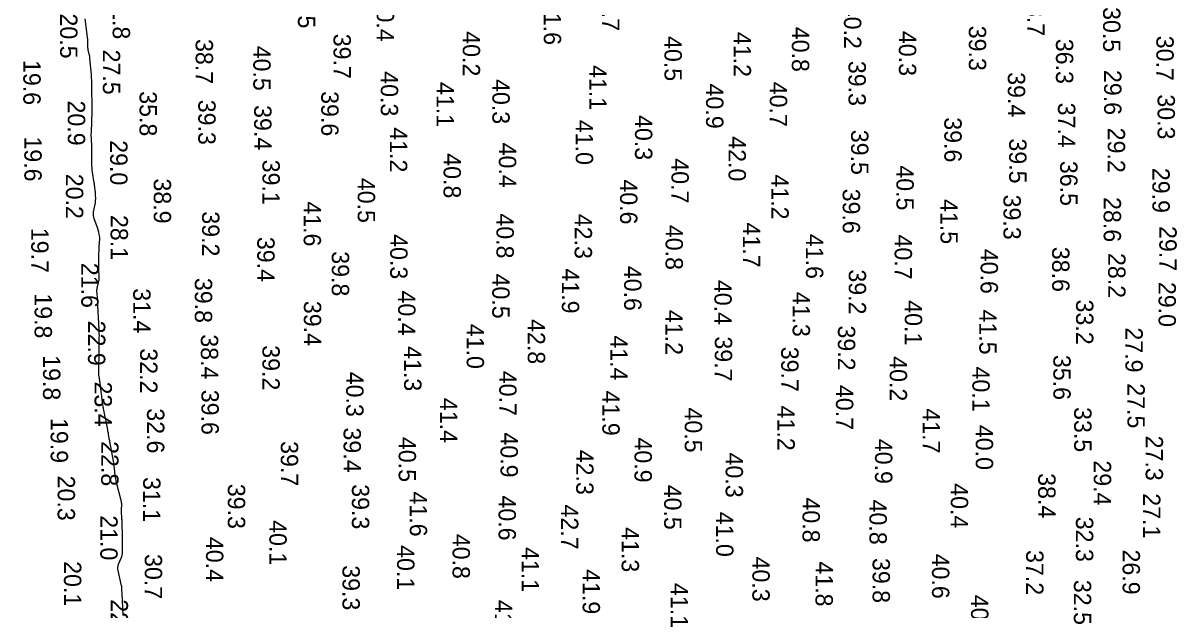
# Model space of a CAD drawing. Extents: x 1178573 to 1187098, y 693282 to 751751.
# Drawn here: x 1181240 to 1182072, y 696180 to 696604 of the extents above; entities that cross this region are included whole.
import ezdxf

# ---------------------------------------------------------------- set-up
doc = ezdxf.new("R2010")
doc.units = 0
doc.layers.add('V-HYDS-MAJR', color=7, linetype='Continuous')
doc.layers.add('V-HYDS-SOUN', color=7, linetype='Continuous')

msp = doc.modelspace()

# ---------------------------------------------------------------- linework, layer by layer
at = {"layer": 'V-HYDS-MAJR'}
msp.add_lwpolyline([(1181311.87, 696176.51), (1181311.14, 696192.46), (1181311.13, 696192.69), (1181311.11, 696192.92), (1181311.08, 696193.15), (1181311.06, 696193.38), (1181310.94, 696194.29), (1181310.91, 696194.52), (1181310.9, 696194.75), (1181310.89, 696194.98), (1181310.89, 696195.21), (1181310.92, 696196.65), (1181310.92, 696196.96), (1181310.9, 696197.27), (1181310.86, 696197.59), (1181310.8, 696197.9), (1181308.26, 696208.79), (1181308.08, 696209.95), (1181308.08, 696211.1), (1181308.27, 696212.23), (1181308.64, 696213.35), (1181310.47, 696217.79), (1181310.87, 696218.91), (1181311.16, 696220.05), (1181311.34, 696221.22), (1181311.4, 696222.41), (1181311.44, 696227.33), (1181311.44, 696228.54), (1181311.44, 696229.76), (1181311.42, 696230.98), (1181311.4, 696232.2), (1181311.1, 696244.47), (1181311.08, 696245.18), (1181311.05, 696245.9), (1181311.01, 696246.61), (1181310.96, 696247.32), (1181310.77, 696250.18), (1181310.73, 696250.89), (1181310.71, 696251.6), (1181310.7, 696252.32), (1181310.72, 696253.03), (1181310.82, 696256.22), (1181310.82, 696256.99), (1181310.76, 696257.75), (1181310.65, 696258.51), (1181310.49, 696259.26), (1181307.2, 696272.37), (1181306.9, 696273.64), (1181306.64, 696274.92), (1181306.42, 696276.21), (1181306.25, 696277.5), (1181305.63, 696282.69), (1181305.47, 696283.99), (1181305.28, 696285.28), (1181305.08, 696286.57), (1181304.85, 696287.86), (1181302.48, 696300.71), (1181302.33, 696301.51), (1181302.19, 696302.31), (1181302.05, 696303.11), (1181301.91, 696303.91), (1181301.36, 696307.12), (1181301.22, 696307.92), (1181301.08, 696308.72), (1181300.93, 696309.52), (1181300.77, 696310.32), (1181297.73, 696325.75), (1181297.66, 696326.12), (1181297.59, 696326.49), (1181297.53, 696326.86), (1181297.47, 696327.22), (1181297.24, 696328.7), (1181297.18, 696329.07), (1181297.13, 696329.45), (1181297.07, 696329.82), (1181297.02, 696330.19), (1181294.96, 696345.94), (1181294.88, 696346.52), (1181294.81, 696347.1), (1181294.74, 696347.68), (1181294.68, 696348.27), (1181294.43, 696350.59), (1181294.38, 696351.18), (1181294.35, 696351.76), (1181294.33, 696352.34), (1181294.33, 696352.93), (1181294.55, 696366.87), (1181294.57, 696368.13), (1181294.59, 696369.4), (1181294.61, 696370.67), (1181294.63, 696371.93), (1181294.71, 696377), (1181294.72, 696378.26), (1181294.71, 696379.53), (1181294.67, 696380.79), (1181294.62, 696382.06), (1181294.09, 696391.88), (1181294.04, 696392.86), (1181293.99, 696393.83), (1181293.95, 696394.81), (1181293.91, 696395.78), (1181293.75, 696399.69), (1181293.71, 696400.66), (1181293.65, 696401.64), (1181293.59, 696402.61), (1181293.52, 696403.59), (1181293.01, 696410.4), (1181292.98, 696411.2), (1181293.03, 696412), (1181293.14, 696412.79), (1181293.32, 696413.57), (1181294.18, 696416.7), (1181294.37, 696417.48), (1181294.5, 696418.27), (1181294.57, 696419.07), (1181294.58, 696419.87), (1181294.41, 696427.49), (1181294.39, 696429.03), (1181294.38, 696430.57), (1181294.4, 696432.11), (1181294.43, 696433.65), (1181294.67, 696443.2), (1181294.69, 696443.78), (1181294.72, 696444.35), (1181294.77, 696444.92), (1181294.82, 696445.48), (1181295.07, 696447.76), (1181295.11, 696448.33), (1181295.1, 696448.89), (1181295.05, 696449.45), (1181294.95, 696450.01), (1181294.31, 696452.94), (1181294.15, 696453.61), (1181293.97, 696454.27), (1181293.77, 696454.93), (1181293.55, 696455.58), (1181291.06, 696462.41), (1181290.69, 696463.68), (1181290.49, 696464.97), (1181290.47, 696466.27), (1181290.62, 696467.58), (1181291.83, 696474.11), (1181291.94, 696474.82), (1181292.02, 696475.53), (1181292.06, 696476.24), (1181292.07, 696476.96), (1181292.03, 696479.82), (1181292.01, 696480.54), (1181291.97, 696481.25), (1181291.91, 696481.96), (1181291.82, 696482.68), (1181291.44, 696485.53), (1181291.34, 696486.24), (1181291.24, 696486.95), (1181291.13, 696487.66), (1181291.02, 696488.37), (1181289.8, 696496.1), (1181289.59, 696497.63), (1181289.44, 696499.16), (1181289.36, 696500.69), (1181289.33, 696502.24), (1181289.34, 696509.88), (1181289.34, 696511.13), (1181289.32, 696512.38), (1181289.28, 696513.63), (1181289.23, 696514.88), (1181289, 696519.89), (1181288.95, 696521.14), (1181288.94, 696522.39), (1181288.94, 696523.64), (1181288.98, 696524.89), (1181289.55, 696539.87), (1181289.56, 696540.01), (1181289.56, 696540.16), (1181289.57, 696540.3), (1181289.57, 696540.44), (1181289.6, 696541.11), (1181289.6, 696541.21), (1181289.6, 696541.31), (1181289.59, 696541.4), (1181289.59, 696541.5), (1181289.55, 696541.88), (1181289.54, 696541.98), (1181289.54, 696542.08), (1181289.54, 696542.17), (1181289.53, 696542.27), (1181289.4, 696557.69), (1181289.36, 696559.9), (1181289.27, 696562.11), (1181289.15, 696564.32), (1181288.98, 696566.52), (1181287.96, 696578.18), (1181287.88, 696578.96), (1181287.77, 696579.74), (1181287.63, 696580.52), (1181287.47, 696581.29), (1181286.76, 696584.4), (1181286.6, 696585.15), (1181286.5, 696585.9), (1181286.43, 696586.66), (1181286.4, 696587.43), (1181286.38, 696590.5), (1181286.36, 696591.27), (1181286.32, 696592.03), (1181286.26, 696592.79), (1181286.18, 696593.56), (1181284.51, 696606.81)], dxfattribs=at)

# ---------------------------------------------------------------- texts
at = {"layer": 'V-HYDS-SOUN'}
for s, p in [('39.5 ', (1181437.93, 696632.39)), ('41.7 ', (1181657.31, 696630.44)), ('31.8 ', (1181304.34, 696624.5)), ('40.4 ', (1181494.78, 696622.77)), ('38.7 ', (1181963.9, 696626.8)), ('41.6 ', (1181615.25, 696620.37)), ('40.2 ', (1181831.74, 696617.61)), ('30.5 ', (1182018.61, 696615.2)), ('20.5 ', (1181266.44, 696610.6)), ('40.2 ', (1181556.81, 696597.79)), ('41.2 ', (1181752.21, 696597.33)), ('40.8 ', (1181794.16, 696601.01)), ('40.3 ', (1181871.35, 696598.03)), ('39.3 ', (1181921.81, 696601.77)), ('38.7 ', (1181364.2, 696592.19)), ('39.7 ', (1181463.61, 696595.99)), ('40.5 ', (1181702.3, 696594.33)), ('36.3 ', (1181984.61, 696592.35)), ('30.7 ', (1182057.05, 696594.55)), ('27.5 ', (1181297.25, 696584.55)), ('40.5 ', (1181405.75, 696587.38)), ('19.6 ', (1181239.89, 696577.06)), ('41.1 ', (1181648.07, 696573.41)), ('39.3 ', (1181835.03, 696576.44)), ('40.3 ', (1181497.7, 696568.93)), ('40.3 ', (1181578.18, 696563.31)), ('39.4 ', (1181949.93, 696568.28)), ('29.6 ', (1182019.35, 696569.88)), ('41.1 ', (1181537.93, 696561.21)), ('40.9 ', (1181732.29, 696560.03)), ('40.7 ', (1181778.27, 696561.38)), ('20.9 ', (1181271.99, 696547.83)), ('35.8 ', (1181323.72, 696554.56)), ('39.3 ', (1181366.07, 696548.39)), ('39.6 ', (1181454.75, 696554.59)), ('30.3 ', (1182057.93, 696552.29)), ('39.4 ', (1181406.39, 696544.53)), ('37.4 ', (1181986.08, 696546.3)), ('41.0 ', (1181638.31, 696533.9)), ('40.3 ', (1181681.03, 696537.36)), ('39.6 ', (1181904.13, 696535.76)), ('41.2 ', (1181504.28, 696528.54)), ('42.0 ', (1181748.52, 696522.05)), ('39.5 ', (1181836.88, 696526.71)), ('29.2 ', (1182022, 696528.24)), ('19.6 ', (1181240.64, 696521.94)), ('29.0 ', (1181302.52, 696519.23)), ('40.4 ', (1181582.84, 696517.46)), ('39.5 ', (1181950.89, 696520.48)), ('39.1 ', (1181412.38, 696505.17)), ('40.8 ', (1181542.98, 696509.8)), ('40.7 ', (1181707.31, 696506.16)), ('40.5 ', (1181869.56, 696501.09)), ('36.5 ', (1181987.67, 696504.31)), ('29.9 ', (1182054.2, 696499.27)), ('20.2 ', (1181270.62, 696495.01)), ('38.9 ', (1181333.96, 696491.63)), ('40.5 ', (1181481.07, 696492.07)), ('40.6 ', (1181670.27, 696490.97)), ('41.2 ', (1181779.38, 696494.55)), ('39.6 ', (1181830.83, 696484.25)), ('41.6 ', (1181442.09, 696475.13)), ('41.5 ', (1181901.35, 696476.78)), ('39.3 ', (1181946.78, 696479.98)), ('28.6 ', (1182019.05, 696478.21)), ('28.1 ', (1181302.86, 696465.31)), ('39.2 ', (1181368.82, 696467.94)), ('40.8 ', (1181581.14, 696466.43)), ('42.3 ', (1181637.53, 696466.14)), ('19.7 ', (1181245.6, 696456.06)), ('40.8 ', (1181703.09, 696458.16)), ('41.7 ', (1181758.88, 696459.9)), ('29.7 ', (1182059.18, 696457.31)), ('39.4 ', (1181408.62, 696449.51)), ('40.3 ', (1181504.49, 696451.47)), ('41.6 ', (1181804.32, 696451.7)), ('40.7 ', (1181868.3, 696451.18)), ('39.8 ', (1181462.37, 696439.14)), ('40.6 ', (1181930.31, 696440.94)), ('38.6 ', (1181981.88, 696442.32)), ('21.6 ', (1181281.69, 696430.8)), ('28.2 ', (1182022.29, 696437.89)), ('40.5 ', (1181578.09, 696423.01)), ('41.9 ', (1181628.28, 696426.73)), ('40.6 ', (1181673.22, 696428.67)), ('39.2 ', (1181835.19, 696426.04)), ('39.8 ', (1181363.59, 696419.91)), ('40.4 ', (1181738.28, 696418.48)), ('29.0 ', (1182058.62, 696417.03)), ('19.8 ', (1181248.04, 696408.79)), ('31.4 ', (1181319.15, 696412.47)), ('40.4 ', (1181510.23, 696410.8)), ('41.3 ', (1181794.74, 696409.94)), ('39.4 ', (1181442.22, 696403.35)), ('41.2 ', (1181703, 696396.81)), ('40.1 ', (1181875.63, 696403.79)), ('41.5 ', (1181929.33, 696397.12)), ('33.2 ', (1181999.13, 696404.29)), ('22.9 ', (1181286.52, 696389.07)), ('42.8 ', (1181603.71, 696390.22)), ('41.0 ', (1181559.64, 696386.82)), ('39.2 ', (1181827.38, 696385.59)), ('27.9 ', (1182034.75, 696384.21)), ('38.4 ', (1181367.94, 696379.24)), ('41.4 ', (1181663.22, 696378.48)), ('39.7 ', (1181738.61, 696377.72)), ('19.8 ', (1181254.11, 696364.17)), ('32.2 ', (1181324.13, 696369.12)), ('39.2 ', (1181412.32, 696371.35)), ('41.3 ', (1181514.53, 696370.73)), ('39.7 ', (1181786.48, 696370.27)), ('40.2 ', (1181864.75, 696363.44)), ('35.6 ', (1181982.77, 696364.37)), ('40.1 ', (1181924.35, 696355.99)), ('40.3 ', (1181472.73, 696352.26)), ('40.7 ', (1181583.13, 696352.95)), ('23.4 ', (1181291.27, 696345.18)), ('39.6 ', (1181368.37, 696339.23)), ('41.9 ', (1181657.48, 696338.64)), ('40.7 ', (1181825.98, 696342.71)), ('27.5 ', (1182036.19, 696343.94)), ('41.4 ', (1181540.48, 696333.4)), ('32.6 ', (1181329.1, 696325.88)), ('40.5 ', (1181716.93, 696326.45)), ('41.2 ', (1181783.78, 696327.81)), ('41.7 ', (1181888.54, 696325.85)), ('33.5 ', (1181997.77, 696326.75)), ('19.9 ', (1181259.62, 696318.89)), ('40.0 ', (1181926.8, 696313.92)), ('39.4 ', (1181470.86, 696312.05)), ('40.5 ', (1181510.6, 696305.22)), ('40.9 ', (1181584.06, 696308.46)), ('27.3 ', (1182049.34, 696306.16)), ('22.8 ', (1181296.07, 696302.19)), ('39.7 ', (1181425.62, 696302.23)), ('40.9 ', (1181680.68, 696304.82)), ('40.9 ', (1181854.14, 696303.87)), ('42.3 ', (1181638.61, 696295.99)), ('40.3 ', (1181746.42, 696293.93)), ('29.4 ', (1182011.94, 696288.33)), ('20.3 ', (1181264.66, 696277.32)), ('31.1 ', (1181326.32, 696276.3)), ('40.4 ', (1181908.79, 696271.82)), ('38.4 ', (1181971.84, 696279.11)), ('39.3 ', (1181387.4, 696271.42)), ('39.3 ', (1181476.86, 696271.12)), ('41.6 ', (1181518.6, 696265.87)), ('40.5 ', (1181702.07, 696270.78)), ('27.1 ', (1182047.48, 696264.59)), ('40.6 ', (1181582.64, 696263.02)), ('42.7 ', (1181627.68, 696256.49)), ('40.8 ', (1181801.84, 696261.58)), ('40.8 ', (1181850.13, 696260.03)), ('21.0 ', (1181295.4, 696248.73)), ('41.0 ', (1181739.53, 696251.28)), ('32.3 ', (1181999.04, 696247.67)), ('40.1 ', (1181417.33, 696245.2)), ('41.3 ', (1181671.42, 696240.19)), ('40.4 ', (1181371.65, 696233.14)), ('40.8 ', (1181549.48, 696235.36)), ('40.1 ', (1181509.46, 696227.19)), ('41.1 ', (1181599.32, 696225.81)), ('37.2 ', (1181963.14, 696223.65)), ('26.9 ', (1182032.71, 696224.04)), ('20.1 ', (1181269.2, 696215.64)), ('30.7 ', (1181327.49, 696220.76)), ('40.3 ', (1181765.68, 696218.93)), ('41.8 ', (1181811.22, 696215.45)), ('39.8 ', (1181852.4, 696217.94)), ('40.6 ', (1181895.24, 696221.03)), ('39.3 ', (1181470.07, 696212.69)), ('41.9 ', (1181643.28, 696209.9)), ('41.1 ', (1181706.8, 696199.92)), ('32.5 ', (1181997.54, 696202.14)), ('40.0 ', (1181923.39, 696191.41)), ('22.4 ', (1181302.91, 696188.16)), ('41.2 ', (1181579.97, 696187.72))]:
    msp.add_text(s, height=12.5, rotation=270, dxfattribs=at).set_placement(p)

doc.saveas('drawing.dxf')
